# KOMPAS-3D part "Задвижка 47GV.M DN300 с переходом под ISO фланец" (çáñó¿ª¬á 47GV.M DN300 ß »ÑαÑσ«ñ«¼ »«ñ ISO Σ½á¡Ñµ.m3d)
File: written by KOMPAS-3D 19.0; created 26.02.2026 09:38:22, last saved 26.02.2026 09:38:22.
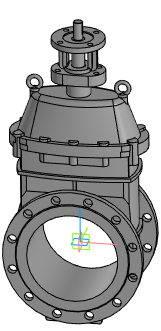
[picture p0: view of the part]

Document properties: Автор: Энергия; Полное имя файла: 47GV.M DN300\Задвижка 47GV.M DN300 с маховиком.a3d

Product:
- Part/product: Задвижка 47GV.M DN300 с переходом под ISO фланец
    Масса: 233.956
  - Component: Задвижка с обрезиненным клином DN300. Сборочный чертеж  | designation DR.47GVM.300.16.00.000СБ  | pos. 0  | Масса: 108.933; Раздел спецификации: Документация; Форматы листов документа: 2xA3; source file: ..\..\47GVM\DR.47GVM.300.16.00.000\DR.47GVM.300.16.00.000 СБ - Задвижка с обрезиненным клином DN300.cdw

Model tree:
1. Операция без истории:1

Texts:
  Точка начала. Х
  Точка начала. Y
  Точка начала. Z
